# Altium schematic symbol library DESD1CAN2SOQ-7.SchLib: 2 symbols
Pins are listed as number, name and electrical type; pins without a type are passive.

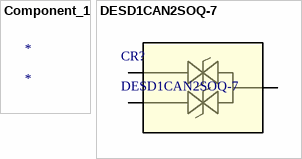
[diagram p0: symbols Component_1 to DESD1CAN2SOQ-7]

## Component_1
designator *

## DESD1CAN2SOQ-7
designator CR?
No Description Available; Mfr_Name: Diodes Inc; Type: DEV
footprint DIODE3_DESD1CAN2SOQ-7_DIO
pins: 1, 2, 3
